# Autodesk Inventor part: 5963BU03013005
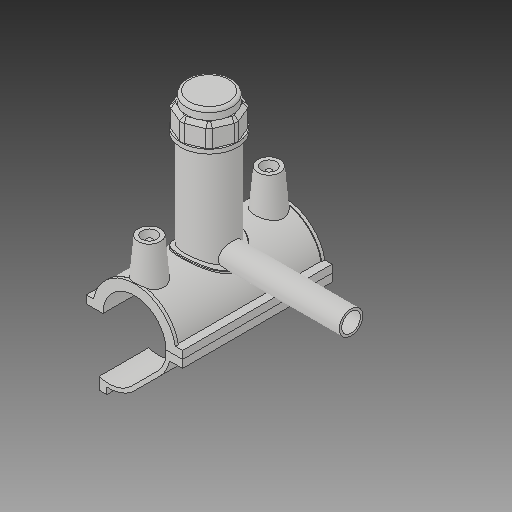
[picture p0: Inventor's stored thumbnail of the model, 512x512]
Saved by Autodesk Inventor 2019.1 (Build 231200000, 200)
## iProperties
Created: 2017-07
Part Number: 5963BU03013005
Material: Generic
Description: PLASSON TAPPING SADDLE 1 1/4''IPS x 1/2''CTS
Document SubType Name: Modeling
Designer: KIM
Mass: 1712.7 g
Surface Area: 2671.49 cm^2
Volume: 1712.7 cm^3
Density: 1 g/cm^3
Appearance: Default
Author: KIM
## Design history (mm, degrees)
derived "5963B.ipt"
feature "Solid1::5963B.ipt"
feature "Solid2::5963B.ipt"
feature "Solid4::5963B.ipt"
feature "Solid5::5963B.ipt"
tag "TaggingFeature1"
body "Solid1"
body "Solid2"
other parameters: "d_" = 42.1, "B_" = 64.516, "L_" = 100.076, "d_t" = 6, "H_2" = 93.726, "H_1" = 6.858, "d_1" = 15.8, "H_" = 94.996, "d1" = 54.73, "d148" = 0.6315, "d160" = 0.6315, "d169" = 3.2805, "d192" = 6.1236, "d0" = 42.1, "d2" = 64.516, "d3" = 10.525, "d4" = 100.076, "d5" = 0, "d6" = 0.1, "d8" = 0, "d19" = 6, "d20" = 6, "d21" = 60.0456, "d23" = 0, "d24" = 30.0228, "d26" = 0, "d29" = 3, "d30" = 14.03333, "d31" = 6, "d32" = 0, "d33" = 0, "d34" = 0.6, "d40" = 28.4596, "d41" = 37.89, "d43" = 0, "d45" = 0, "d47" = 87.4106, "d70" = 15, "d72" = 0, "d73" = 6, "d75" = 5, "d76" = 0, "d77" = 2.105, "d78" = 51.05, "d79" = 15, "d80" = 40.0304, "d82" = 5 deg, "d84" = 4, "d85" = 14, "d86" = 0, "d87" = 3, "d88" = 0, "d89" = 1, "d90" = 1, "d91" = 80.0608, "d92" = 0, "d93" = 0.5, "d94" = 22.15789, "d96" = 55.8246, "d97" = 2.00152, "d98" = 0, "d102" = 0.421, "d120" = 140 deg, "d121" = 24.228, "d122" = 20 deg, "d123" = 109.46, "d124" = 32.838, "d126" = 0, "d143" = 43.363, "d145" = 9.71538, "d149" = 0.6315, "d150" = 10.68692, "d153" = 100.076, "d154" = 0, "d156" = 27.365, "d157" = 160 deg, "d159" = 2.526, "d161" = 0.6315, "d162" = 60.0456, "d163" = 0, "d164" = 21.05, "d167" = 4.21, "d168" = 26.69756, "d170" = 3.2805, "d172" = 0, "d173" = 1, "d175" = 21.05, "d176" = 20 deg, "d177" = 2.947, "d178" = 12.63, "d180" = 0, "d183" = 5.052, "d184" = 2.3576, "d185" = 32.5247, "d186" = 32.5247, "d187" = 27.365, "d188" = 3.789, "d189" = 2.947, "d190" = 0, "d191" = 41.0475, "d193" = 6.1236, "d194" = 3.50266, "d195" = 90 deg, "d197" = 0, "d199" = 0, "d200" = 6.315, "d202" = 0, "d203" = 93.726, "d204" = 35.9955, "d205" = 26.523, "d206" = 32.2065, "d207" = 70.2945, "d208" = 73.10628, "d209" = 87.16518, "d210" = 32.5854, "d211" = 37.89, "d212" = 30.312, "d213" = -0.9378, "d216" = 0, "d217" = 4.21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
